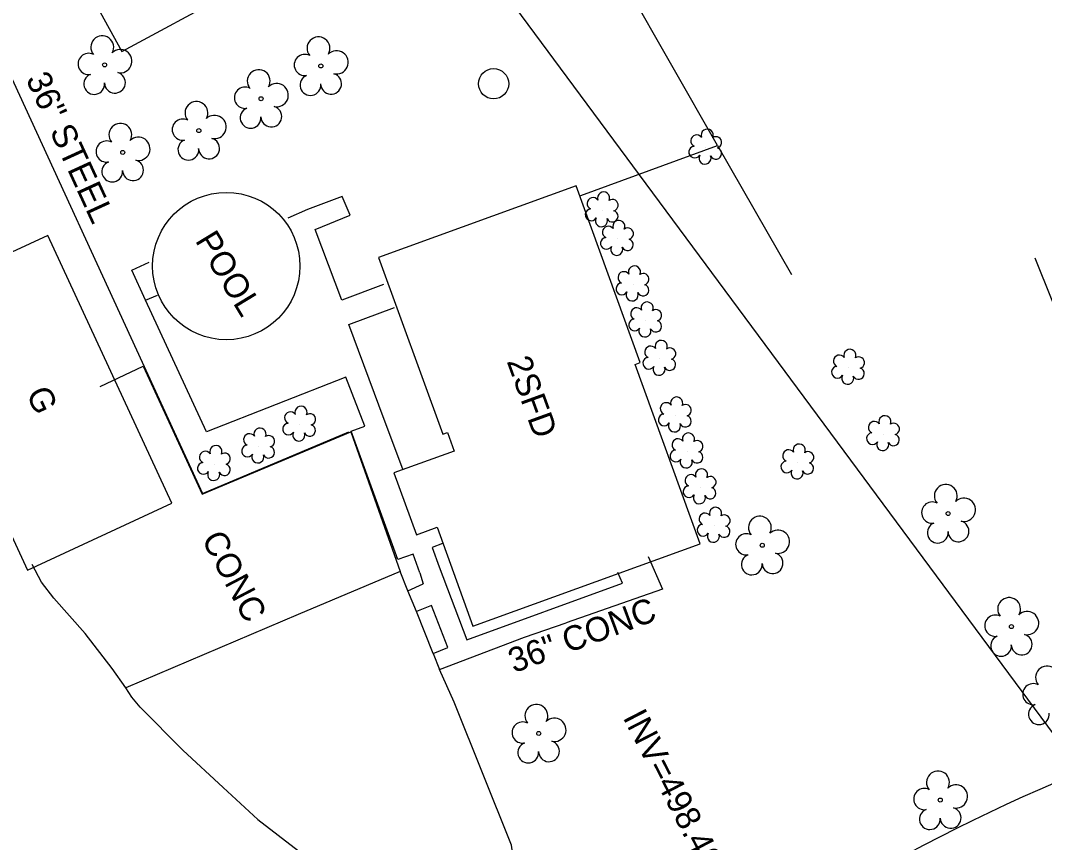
# Model space of a CAD drawing. Extents: x 1534145 to 1537876, y 509021 to 513201.
# Drawn here: x 1536446 to 1536612.8, y 511445.5 to 511579.4 of the extents above; entities that cross this region are included whole.
import ezdxf

# ---------------------------------------------------------------- set-up
doc = ezdxf.new("R2010")
doc.units = 0
for name, color, linetype in [('Exist Building', 7, 'Continuous'), ('Exist Building Text', 7, 'Continuous'), ('Exist Horizontal Alignment', 7, 'Continuous'), ('Exist Hydro Pool or Reservoir', 7, 'Continuous'), ('Exist Hydro Pool or Reservoir Text', 7, 'Continuous'), ('Exist Other Culture Area Outline', 7, 'Continuous'), ('Exist Other Culture Area Outline Text', 7, 'Continuous'), ('Exist Other Culture Fence Line', 7, 'Continuous'), ('Exist Other Culture Fence Line Text', 7, 'Continuous'), ('Exist Property Line', 7, 'Continuous'), ('Exist Right of Way Line', 7, 'Continuous'), ('Exist Roads EOP Other', 7, 'Continuous'), ('Exist Roads EOP Other Text', 7, 'Continuous'), ('Exist Roads Soil', 7, 'Continuous'), ('Exist Structure Minor Pipes CMP 15 Inch Invert', 7, 'Continuous'), ('Exist Utilities Other Pole CELL', 7, 'Continuous'), ('Exist Vegetation Shrub CELL', 7, 'Continuous'), ('Exist Vegetation Tree CELL', 7, 'Continuous')]:
    doc.layers.add(name, color=color, linetype=linetype)

msp = doc.modelspace()

# ---------------------------------------------------------------- linework, layer by layer
at = {"layer": 'Exist Building'}
for points in [[(1536519.74, 511480.73), (1536556.74, 511494.14), (1536546.14, 511523.38), (1536546.96, 511523.68), (1536536.53, 511552.44), (1536504.38, 511540.79), (1536514.82, 511512), (1536515.6, 511512.28), (1536516.7, 511509.26), (1536506.87, 511505.7), (1536510.53, 511495.62), (1536513.9, 511496.84)], [(1536426.98, 511533.49), (1536447.19, 511489.86), (1536470.71, 511500.76), (1536450.5, 511544.38)]]:
    msp.add_lwpolyline(points, close=True, dxfattribs=at)
at = {"layer": 'Exist Horizontal Alignment'}
msp.add_arc((1536795.22, 511072.63), 390, 105.6865, 140.1365, dxfattribs=at)
at = {"layer": 'Exist Hydro Pool or Reservoir'}
msp.add_circle((1536479.56, 511539.39), 12, dxfattribs=at)
at = {"layer": 'Exist Other Culture Area Outline'}
for points in [[(1536453.4, 511590.97), (1536462.57, 511574.36), (1536480.06, 511583.83), (1536471.21, 511600.37), (1536453.4, 511590.97)], [(1536505.17, 511536.38), (1536498.36, 511533.85), (1536494.03, 511545.37), (1536499.74, 511547.66), (1536498.43, 511550.75), (1536492.81, 511548.58), (1536489.57, 511547.22)], [(1536464.15, 511538.71), (1536467.02, 511540.02)], [(1536466.42, 511533.84), (1536464.15, 511538.71)], [(1536466.42, 511533.84), (1536468.37, 511534.64)], [(1536511.11, 511489.4), (1536510.01, 511492.45), (1536507.52, 511491.59), (1536499.9, 511512.5), (1536502.14, 511513.33), (1536499.06, 511521.28), (1536476.35, 511512.36), (1536466.42, 511533.84)], [(1536508.31, 511506.32), (1536505.29, 511514.39), (1536499.53, 511529.86), (1536506.94, 511532.62)], [(1536514.8, 511494.18), (1536513.08, 511493.55), (1536514.23, 511490.39)], [(1536548.27, 511492.09), (1536550.63, 511486.73), (1536534.94, 511481.25)], [(1536514.23, 511490.39), (1536518.72, 511478.48), (1536544.1, 511487.75), (1536543.33, 511489.46)], [(1536511.11, 511489.4), (1536511.65, 511487.6)], [(1536513.26, 511476.3), (1536515.64, 511477.23), (1536512.97, 511484.08), (1536510.56, 511483.13), (1536509.13, 511486.5), (1536511.65, 511487.6)], [(1536528.14, 511478.91), (1536534.94, 511481.25)], [(1536513.26, 511476.3), (1536514.31, 511473.66), (1536528.14, 511478.91)]]:
    msp.add_lwpolyline(points, dxfattribs=at)
at = {"layer": 'Exist Other Culture Fence Line'}
for points in [[(1536559.59, 511559.04), (1536544.69, 511585.14), (1536518.03, 511632.02), (1536473.07, 511609.73), (1536435.1, 511590.69), (1536475.67, 511502.32), (1536499.5, 511512.38)], [(1536537.33, 511550.89), (1536559.59, 511559.04), (1536571.62, 511538.01)]]:
    msp.add_lwpolyline(points, dxfattribs=at)
at = {"layer": 'Exist Property Line'}
msp.add_line((1536618.84, 511457.03), (1536338.99, 511835.06), dxfattribs=at)
at = {"layer": 'Exist Right of Way Line'}
msp.add_arc((1536740.96, 511161.67), 319.6, 105.6865, 140.1365, dxfattribs=at)
at = {"layer": 'Exist Roads EOP Other'}
for points in [[(1536616.95, 511526.63), (1536611.34, 511540.67)], [(1536459, 511519.79), (1536466.04, 511523.08), (1536475.62, 511502.23), (1536499.85, 511512.4), (1536507.89, 511489.61)], [(1536507.89, 511489.61), (1536491.28, 511482.62), (1536463.18, 511470.66), (1536460.98, 511473.82), (1536456.57, 511479.53), (1536451.48, 511485.27), (1536449.47, 511487.87), (1536447.95, 511490.75)]]:
    msp.add_lwpolyline(points, dxfattribs=at)
at = {"layer": 'Exist Roads Soil'}
for points in [[(1536509.13, 511486.5), (1536507.89, 511489.61)], [(1536513.26, 511476.3), (1536510.56, 511483.13)], [(1536559.52, 511395.55), (1536556.28, 511395.95), (1536552.65, 511395.88), (1536548.04, 511397.86), (1536544.5, 511401.73), (1536542.08, 511405.87), (1536537.59, 511413.88), (1536532.56, 511423.21), (1536528.7, 511432.08), (1536527.05, 511438.17), (1536526.04, 511445.06), (1536516.68, 511468.36), (1536514.31, 511473.66)], [(1536479.05, 511454.45), (1536472.48, 511460.54), (1536465.52, 511467.56), (1536464.15, 511469.15), (1536463.18, 511470.66)], [(1536479.05, 511454.45), (1536484.68, 511449.25), (1536503.86, 511434.49), (1536509.05, 511430.81), (1536513.11, 511426.58), (1536517.23, 511423.29), (1536523.59, 511412.59), (1536531.84, 511396.62), (1536534.97, 511388.37), (1536535.29, 511384.16)]]:
    msp.add_lwpolyline(points, dxfattribs=at)
at = {"layer": 'Exist Utilities Other Pole CELL'}
msp.add_circle((1536523.1, 511569.09), 2.46, dxfattribs=at)
at = {"layer": 'Exist Vegetation Shrub CELL'}
for p, q in [((1536557.66, 511558.67), (1536557.66, 511558.67)), ((1536540.79, 511548.44), (1536540.79, 511548.44)), ((1536543.27, 511543.8), (1536543.27, 511543.8)), ((1536545.81, 511536.39), (1536545.81, 511536.39)), ((1536547.88, 511530.51), (1536547.88, 511530.51)), ((1536550.17, 511524.26), (1536550.17, 511524.26)), ((1536580.91, 511522.8), (1536580.91, 511522.8)), ((1536491.5, 511513.54), (1536491.5, 511513.54)), ((1536552.7, 511515.04), (1536552.7, 511515.04)), ((1536586.61, 511511.99), (1536586.61, 511511.99)), ((1536484.83, 511509.98), (1536484.83, 511509.98)), ((1536554.61, 511509.17), (1536554.61, 511509.17)), ((1536477.63, 511507.13), (1536477.63, 511507.13)), ((1536572.65, 511507.37), (1536572.65, 511507.37)), ((1536556.73, 511503.33), (1536556.73, 511503.33)), ((1536559.02, 511497.06), (1536559.02, 511497.06))]:
    msp.add_line(p, q, dxfattribs=at)
for centre, radius, start, end in [((1536556.18, 511559.79), 0.968, 35.8908, 245.4216), ((1536557.89, 511560.71), 0.99, 334.8391, 200.4717), ((1536559.33, 511559.54), 0.929, 284.4567, 126.0861), ((1536555.86, 511557.96), 0.955, 95.1099, 327.9534), ((1536559.3, 511557.74), 0.937, 204.9913, 73.4601), ((1536557.53, 511556.98), 0.984, 151.2797, 21.387), ((1536539.31, 511549.57), 0.968, 35.8908, 245.4216), ((1536541.02, 511550.48), 0.99, 334.8391, 200.4717), ((1536542.46, 511549.31), 0.929, 284.4567, 126.0861), ((1536538.99, 511547.74), 0.955, 95.1099, 327.9534), ((1536542.43, 511547.51), 0.937, 204.9913, 73.4601), ((1536540.66, 511546.76), 0.984, 151.2797, 21.387), ((1536543.5, 511545.84), 0.99, 334.8391, 200.4717), ((1536541.79, 511544.92), 0.968, 35.8908, 245.4216), ((1536544.95, 511544.67), 0.929, 284.4567, 126.0861), ((1536541.47, 511543.09), 0.955, 95.1099, 327.9534), ((1536544.91, 511542.87), 0.937, 204.9913, 73.4601), ((1536543.15, 511542.11), 0.984, 151.2797, 21.387), ((1536544.33, 511537.51), 0.968, 35.8908, 245.4216), ((1536546.04, 511538.43), 0.99, 334.8391, 200.4717), ((1536547.48, 511537.26), 0.929, 284.4567, 126.0861), ((1536544.01, 511535.68), 0.955, 95.1099, 327.9534), ((1536545.68, 511534.7), 0.984, 151.2797, 21.387), ((1536547.45, 511535.46), 0.937, 204.9913, 73.4601), ((1536548.11, 511532.55), 0.99, 334.8391, 200.4717), ((1536546.4, 511531.63), 0.968, 35.8908, 245.4216), ((1536549.55, 511531.37), 0.929, 284.4567, 126.0861), ((1536546.08, 511529.8), 0.955, 95.1099, 327.9534), ((1536549.52, 511529.58), 0.937, 204.9913, 73.4601), ((1536547.75, 511528.82), 0.984, 151.2797, 21.387), ((1536550.4, 511526.3), 0.99, 334.8391, 200.4717), ((1536548.69, 511525.39), 0.968, 35.8908, 245.4216), ((1536551.84, 511525.13), 0.929, 284.4567, 126.0861), ((1536581.14, 511524.84), 0.99, 334.8391, 200.4717), ((1536548.37, 511523.56), 0.955, 95.1099, 327.9534), ((1536551.81, 511523.33), 0.937, 204.9913, 73.4601), ((1536579.43, 511523.93), 0.968, 35.8908, 245.4216), ((1536582.58, 511523.67), 0.929, 284.4567, 126.0861), ((1536550.04, 511522.58), 0.984, 151.2797, 21.387), ((1536579.11, 511522.1), 0.955, 95.1099, 327.9534), ((1536582.54, 511521.87), 0.937, 204.9913, 73.4601), ((1536580.78, 511521.12), 0.984, 151.2797, 21.387), ((1536551.22, 511516.17), 0.968, 35.8908, 245.4216), ((1536552.93, 511517.08), 0.99, 334.8391, 200.4717), ((1536554.38, 511515.91), 0.929, 284.4567, 126.0861), ((1536490.02, 511514.67), 0.968, 35.8908, 245.4216), ((1536491.73, 511515.58), 0.99, 334.8391, 200.4717), ((1536493.18, 511514.41), 0.929, 284.4567, 126.0861), ((1536550.9, 511514.34), 0.955, 95.1099, 327.9534), ((1536489.7, 511512.84), 0.955, 95.1099, 327.9534), ((1536493.14, 511512.61), 0.937, 204.9913, 73.4601), ((1536552.57, 511513.36), 0.984, 151.2797, 21.387), ((1536554.34, 511514.11), 0.937, 204.9913, 73.4601), ((1536585.13, 511513.12), 0.968, 35.8908, 245.4216), ((1536586.84, 511514.03), 0.99, 334.8391, 200.4717), ((1536588.28, 511512.86), 0.929, 284.4567, 126.0861), ((1536483.35, 511511.11), 0.968, 35.8908, 245.4216), ((1536485.06, 511512.02), 0.99, 334.8391, 200.4717), ((1536486.5, 511510.85), 0.929, 284.4567, 126.0861), ((1536491.38, 511511.86), 0.984, 151.2797, 21.387), ((1536554.84, 511511.21), 0.99, 334.8391, 200.4717), ((1536584.81, 511511.29), 0.955, 95.1099, 327.9534), ((1536588.25, 511511.06), 0.937, 204.9913, 73.4601), ((1536477.86, 511509.17), 0.99, 334.8391, 200.4717), ((1536483.03, 511509.27), 0.955, 95.1099, 327.9534), ((1536553.13, 511510.29), 0.968, 35.8908, 245.4216), ((1536556.28, 511510.04), 0.929, 284.4567, 126.0861), ((1536572.88, 511509.41), 0.99, 334.8391, 200.4717), ((1536586.48, 511510.31), 0.984, 151.2797, 21.387), ((1536476.15, 511508.25), 0.968, 35.8908, 245.4216), ((1536479.3, 511508), 0.929, 284.4567, 126.0861), ((1536484.7, 511508.3), 0.984, 151.2797, 21.387), ((1536486.47, 511509.05), 0.937, 204.9913, 73.4601), ((1536552.81, 511508.46), 0.955, 95.1099, 327.9534), ((1536556.25, 511508.24), 0.937, 204.9913, 73.4601), ((1536571.17, 511508.5), 0.968, 35.8908, 245.4216), ((1536574.32, 511508.24), 0.929, 284.4567, 126.0861), ((1536475.83, 511506.42), 0.955, 95.1099, 327.9534), ((1536479.27, 511506.2), 0.937, 204.9913, 73.4601), ((1536554.48, 511507.48), 0.984, 151.2797, 21.387), ((1536570.85, 511506.67), 0.955, 95.1099, 327.9534), ((1536574.29, 511506.44), 0.937, 204.9913, 73.4601), ((1536477.5, 511505.44), 0.984, 151.2797, 21.387), ((1536555.25, 511504.45), 0.968, 35.8908, 245.4216), ((1536556.96, 511505.37), 0.99, 334.8391, 200.4717), ((1536558.41, 511504.19), 0.929, 284.4567, 126.0861), ((1536572.52, 511505.69), 0.984, 151.2797, 21.387), ((1536554.93, 511502.62), 0.955, 95.1099, 327.9534), ((1536556.61, 511501.64), 0.984, 151.2797, 21.387), ((1536558.37, 511502.4), 0.937, 204.9913, 73.4601), ((1536559.25, 511499.1), 0.99, 334.8391, 200.4717), ((1536557.54, 511498.19), 0.968, 35.8908, 245.4216), ((1536560.69, 511497.93), 0.929, 284.4567, 126.0861), ((1536557.22, 511496.36), 0.955, 95.1099, 327.9534), ((1536560.66, 511496.13), 0.937, 204.9913, 73.4601), ((1536558.89, 511495.38), 0.984, 151.2797, 21.387)]:
    msp.add_arc(centre, radius, start, end, dxfattribs=at)
at = {"layer": 'Exist Vegetation Tree CELL'}
for p, q in [((1536459.75, 511572.17), (1536459.75, 511572.17)), ((1536494.96, 511571.99), (1536494.96, 511571.99)), ((1536485.22, 511566.65), (1536485.22, 511566.65)), ((1536475.09, 511561.46), (1536475.09, 511561.46)), ((1536462.69, 511557.9), (1536462.69, 511557.9)), ((1536597.14, 511499.08), (1536597.14, 511499.08)), ((1536566.87, 511493.9), (1536566.87, 511493.9)), ((1536607.45, 511480.65), (1536607.45, 511480.65)), ((1536530.45, 511463.25), (1536530.45, 511463.25)), ((1536595.86, 511452.41), (1536595.86, 511452.41))]:
    msp.add_line(p, q, dxfattribs=at)
for centre in [(1536459.75, 511572.17), (1536494.96, 511571.99), (1536485.22, 511566.65), (1536475.09, 511561.46), (1536462.69, 511557.9), (1536597.14, 511499.08), (1536566.87, 511493.9), (1536607.45, 511480.65), (1536530.45, 511463.25), (1536595.86, 511452.41)]:
    msp.add_circle(centre, 0.326, dxfattribs=at)
for centre, radius, start, end in [((1536459.36, 511575.04), 1.86, 330.1651, 219.7134), ((1536494.58, 511574.86), 1.86, 330.1651, 219.7134), ((1536457.14, 511572.32), 1.73, 62.6636, 279.3457), ((1536462.3, 511572.76), 1.9, 257.1011, 134.1999), ((1536492.35, 511572.14), 1.73, 62.6636, 279.3457), ((1536497.51, 511572.58), 1.9, 257.1011, 134.1999), ((1536458.05, 511569.05), 1.69, 111.5671, 6.231), ((1536461.42, 511569.27), 1.7, 181.2822, 74.56), ((1536484.84, 511569.53), 1.86, 330.1651, 219.7134), ((1536493.26, 511568.87), 1.69, 111.5671, 6.231), ((1536496.63, 511569.09), 1.7, 181.2822, 74.56), ((1536482.62, 511566.81), 1.73, 62.6636, 279.3457), ((1536487.77, 511567.24), 1.9, 257.1011, 134.1999), ((1536474.7, 511564.33), 1.86, 330.1651, 219.7134), ((1536483.52, 511563.53), 1.69, 111.5671, 6.231), ((1536486.89, 511563.75), 1.7, 181.2822, 74.56), ((1536477.64, 511562.05), 1.9, 257.1011, 134.1999), ((1536462.31, 511560.77), 1.86, 330.1651, 219.7134), ((1536472.48, 511561.61), 1.73, 62.6636, 279.3457), ((1536465.24, 511558.48), 1.9, 257.1011, 134.1999), ((1536476.76, 511558.56), 1.7, 181.2822, 74.56), ((1536460.09, 511558.05), 1.73, 62.6636, 279.3457), ((1536473.38, 511558.34), 1.69, 111.5671, 6.231), ((1536460.99, 511554.78), 1.69, 111.5671, 6.231), ((1536464.37, 511555), 1.7, 181.2822, 74.56), ((1536596.76, 511501.95), 1.86, 330.1651, 219.7134), ((1536594.54, 511499.23), 1.73, 62.6636, 279.3457), ((1536599.69, 511499.67), 1.9, 257.1011, 134.1999), ((1536566.48, 511496.78), 1.86, 330.1651, 219.7134), ((1536595.44, 511495.96), 1.69, 111.5671, 6.231), ((1536598.82, 511496.18), 1.7, 181.2822, 74.56), ((1536564.26, 511494.06), 1.73, 62.6636, 279.3457), ((1536569.42, 511494.49), 1.9, 257.1011, 134.1999), ((1536565.16, 511490.78), 1.69, 111.5671, 6.231), ((1536568.54, 511491), 1.7, 181.2822, 74.56), ((1536607.07, 511483.52), 1.86, 330.1651, 219.7134), ((1536604.84, 511480.8), 1.73, 62.6636, 279.3457), ((1536610, 511481.23), 1.9, 257.1011, 134.1999), ((1536605.75, 511477.52), 1.69, 111.5671, 6.231), ((1536609.12, 511477.75), 1.7, 181.2822, 74.56), ((1536613.25, 511472.37), 1.86, 330.1651, 219.7134), ((1536611.03, 511469.65), 1.73, 62.6636, 279.3457), ((1536530.07, 511466.12), 1.86, 330.1651, 219.7134), ((1536611.93, 511466.38), 1.69, 111.5671, 6.231), ((1536527.84, 511463.4), 1.73, 62.6636, 279.3457), ((1536533, 511463.84), 1.9, 257.1011, 134.1999), ((1536528.75, 511460.13), 1.69, 111.5671, 6.231), ((1536532.12, 511460.35), 1.7, 181.2822, 74.56), ((1536595.48, 511455.28), 1.86, 330.1651, 219.7134), ((1536593.26, 511452.56), 1.73, 62.6636, 279.3457), ((1536598.41, 511453), 1.9, 257.1011, 134.1999), ((1536594.16, 511449.29), 1.69, 111.5671, 6.231), ((1536597.54, 511449.51), 1.7, 181.2822, 74.56)]:
    msp.add_arc(centre, radius, start, end, dxfattribs=at)

# ---------------------------------------------------------------- texts
at = {"layer": 'Exist Building Text'}
for s, rotation, p in [('2SFD', 289.9217, (1536525.21, 511523.88)), ('G', 294.8536, (1536446.91, 511518.64))]:
    msp.add_text(s, height=4, rotation=rotation, dxfattribs=at).set_placement(p)
at = {"layer": 'Exist Hydro Pool or Reservoir Text'}
msp.add_text('POOL', height=4, rotation=301.2528, dxfattribs=at).set_placement((1536474.4, 511543.55))
at = {"layer": 'Exist Other Culture Area Outline Text'}
msp.add_text('36" CONC', height=4, rotation=20.3739, dxfattribs=at).set_placement((1536526.42, 511473.05))
at = {"layer": 'Exist Other Culture Fence Line Text'}
msp.add_text('36" STEEL', height=4, rotation=294.6632, dxfattribs=at).set_placement((1536446.85, 511569.88))
at = {"layer": 'Exist Roads EOP Other Text'}
msp.add_text('CONC', height=4, rotation=297.6218, dxfattribs=at).set_placement((1536475.46, 511494.95))
at = {"layer": 'Exist Structure Minor Pipes CMP 15 Inch Invert'}
msp.add_text("INV=498.49'", height=4, rotation=297.2825, dxfattribs=at).set_placement((1536544.08, 511465.87))

doc.saveas('drawing.dxf')
